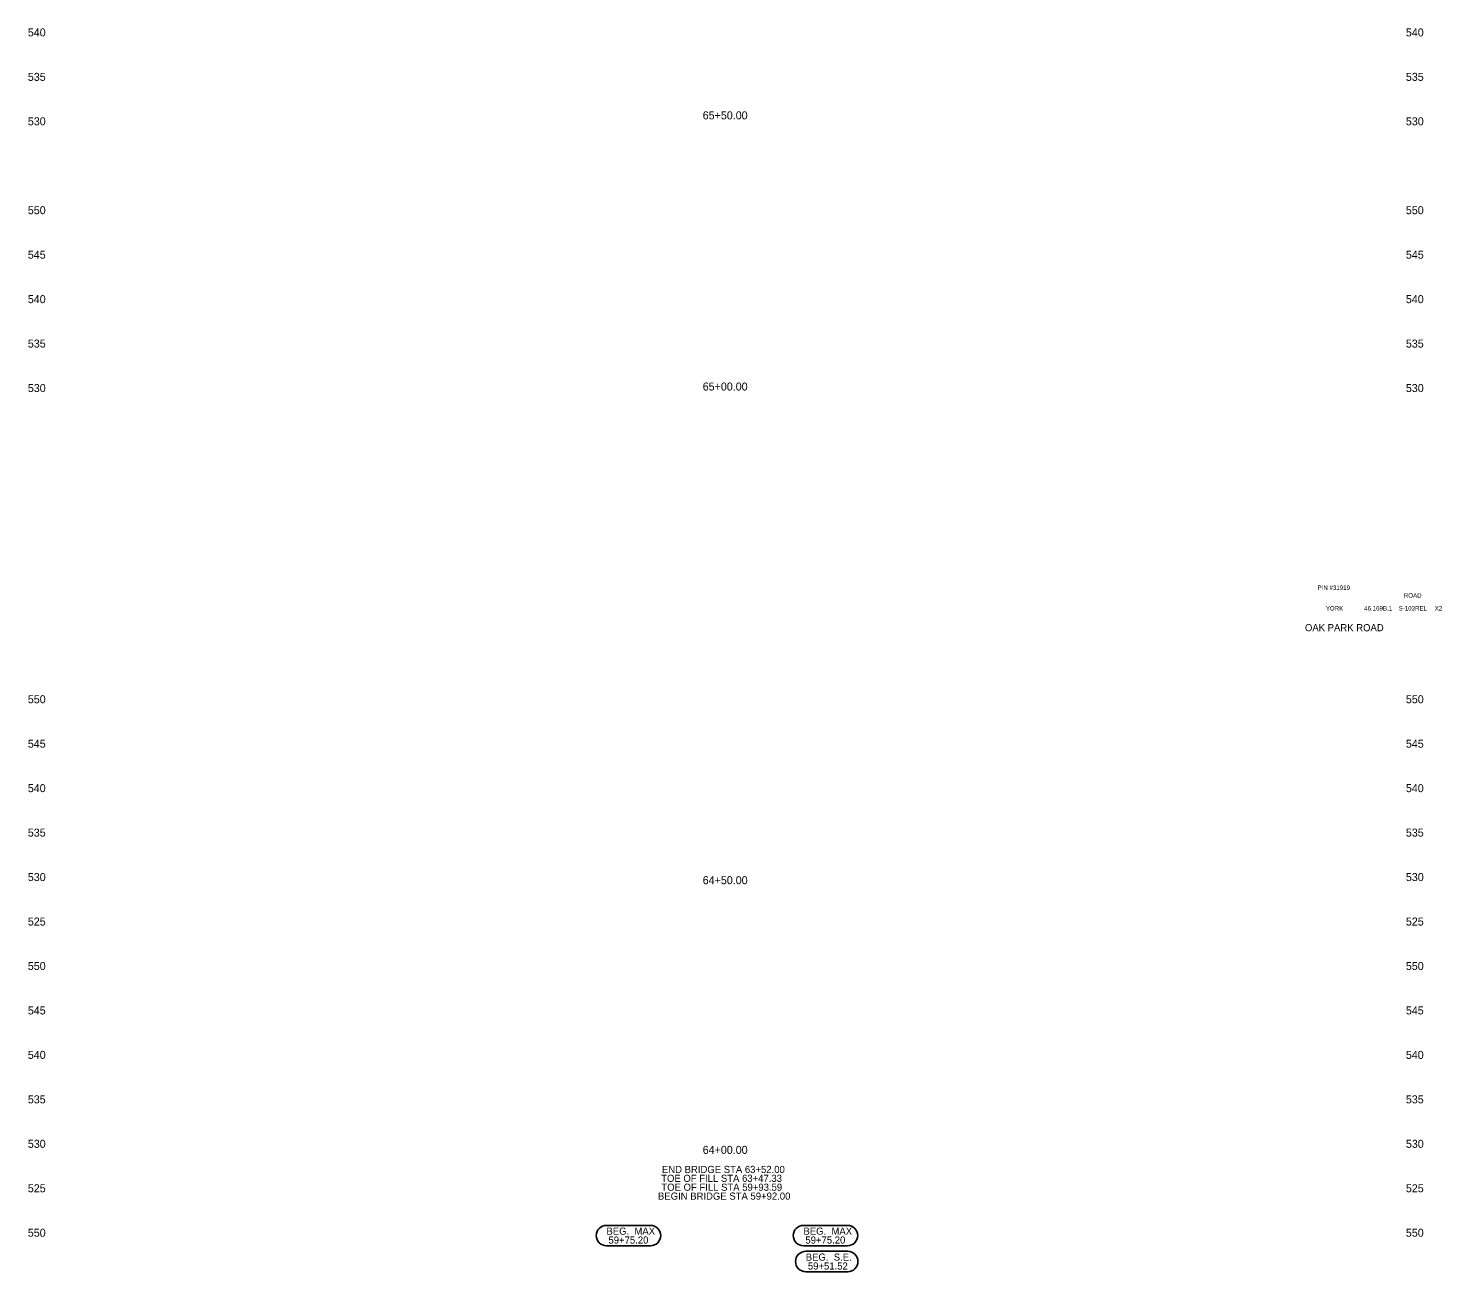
# Model space of a CAD drawing. Extents: x 1001 to 1160, y 1003 to 1563.
# Drawn here: x 1001.5 to 1160.5, y 1141.1 to 1280.9 of the extents above; entities that cross this region are included whole.
import ezdxf

# ---------------------------------------------------------------- set-up
doc = ezdxf.new("R2010")
doc.units = 0
for name, color, linetype in [('Level 25', 7, 'Continuous'), ('Level 41', 7, 'Continuous'), ('Level 56', 7, 'Continuous')]:
    doc.layers.add(name, color=color, linetype=linetype)

msp = doc.modelspace()

# ---------------------------------------------------------------- linework, layer by layer
at = {"layer": 'Level 41'}
for p, q in [((1071.49, 1146.28), (1066.53, 1146.28)), ((1093.64, 1146.28), (1088.69, 1146.28)), ((1066.53, 1143.98), (1071.49, 1143.98)), ((1088.69, 1143.98), (1093.64, 1143.98)), ((1093.67, 1143.36), (1088.95, 1143.36)), ((1088.95, 1141.06), (1093.67, 1141.06))]:
    msp.add_line(p, q, dxfattribs=at)
for centre, start, end in [((1066.53, 1145.13), 90, 270), ((1071.49, 1145.13), 270, 90), ((1088.69, 1145.13), 90, 270), ((1093.64, 1145.13), 270, 90), ((1088.95, 1142.21), 90, 270), ((1093.67, 1142.21), 270, 90)]:
    msp.add_arc(centre, 1.15, start, end, dxfattribs=at)

# ---------------------------------------------------------------- texts
at = {"layer": 'Level 25'}
for s, p in [('65+50.00', (1077.36, 1270.67)), ('65+00.00', (1077.36, 1240.17)), ('64+50.00', (1077.36, 1184.65)), ('64+00.00', (1077.36, 1154.32))]:
    msp.add_text(s, height=0.9, dxfattribs=at).set_placement(p)
at = {"layer": 'Level 41'}
for s, height, p in [('PIN #31919', 0.5, (1146.52, 1217.75)), ('ROAD', 0.5, (1156.22, 1216.88)), ('YORK', 0.5, (1147.45, 1215.43)), ('46.169B.1', 0.5, (1151.76, 1215.43)), ('S-103REL', 0.5, (1155.64, 1215.43)), ('X2', 0.5, (1159.7, 1215.43)), ('OAK PARK ROAD', 0.8, (1145.1, 1213.1)), ('END BRIDGE STA 63+52.00', 0.8, (1072.77, 1152.17)), ('TOE OF FILL STA 63+47.33', 0.8, (1072.69, 1151.17)), ('BEGIN BRIDGE STA 59+92.00', 0.8, (1072.33, 1149.17)), ('TOE OF FILL STA 59+93.59', 0.8, (1072.71, 1150.17)), ('BEG.  MAX', 0.8, (1066.53, 1145.23)), ('59+75.20', 0.8, (1066.76, 1144.23)), ('BEG.  MAX', 0.8, (1088.69, 1145.23)), ('59+75.20', 0.8, (1088.91, 1144.23)), ('BEG.  S.E.', 0.8, (1088.95, 1142.31)), ('59+51.52', 0.8, (1089.19, 1141.31))]:
    msp.add_text(s, height=height, dxfattribs=at).set_placement(p)
at = {"layer": 'Level 56'}
for s, p in [('540', (1001.45, 1280)), ('540', (1156.45, 1280)), ('535', (1001.45, 1275)), ('535', (1156.45, 1275)), ('530', (1001.45, 1270)), ('530', (1156.45, 1270)), ('550', (1001.45, 1260)), ('550', (1156.45, 1260)), ('545', (1001.45, 1255)), ('545', (1156.45, 1255)), ('540', (1001.45, 1250)), ('540', (1156.45, 1250)), ('535', (1001.45, 1245)), ('535', (1156.45, 1245)), ('530', (1001.45, 1240)), ('530', (1156.45, 1240)), ('550', (1001.45, 1205)), ('550', (1156.45, 1205)), ('545', (1001.45, 1200)), ('545', (1156.45, 1200)), ('540', (1001.45, 1195)), ('540', (1156.45, 1195)), ('535', (1001.45, 1190)), ('535', (1156.45, 1190)), ('530', (1001.45, 1185)), ('530', (1156.45, 1185)), ('525', (1001.45, 1180)), ('525', (1156.45, 1180)), ('550', (1001.45, 1175)), ('550', (1156.45, 1175)), ('545', (1001.45, 1170)), ('545', (1156.45, 1170)), ('540', (1001.45, 1165)), ('540', (1156.45, 1165)), ('535', (1001.45, 1160)), ('535', (1156.45, 1160)), ('530', (1001.45, 1155)), ('530', (1156.45, 1155)), ('525', (1001.45, 1150)), ('525', (1156.45, 1150)), ('550', (1001.45, 1145)), ('550', (1156.45, 1145))]:
    msp.add_text(s, height=0.9, dxfattribs=at).set_placement(p)

doc.saveas('drawing.dxf')
